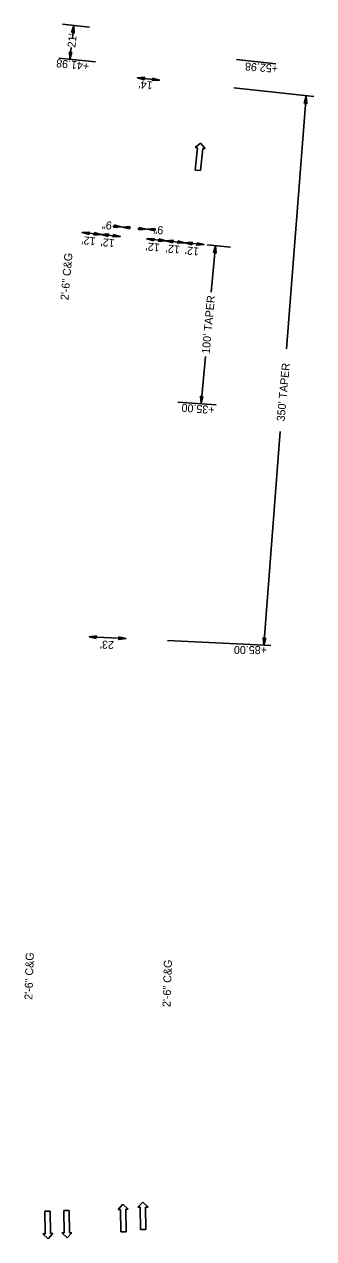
# Model space of a CAD drawing. Extents: x 2320991 to 2332664, y 598057 to 612602.
# Drawn here: x 2328339 to 2328520, y 605365 to 606124 of the extents above; entities that cross this region are included whole.
import ezdxf

# ---------------------------------------------------------------- set-up
doc = ezdxf.new("R2010")
doc.units = 0
for name, color, linetype in [('Prop Dimension', 7, 'Continuous'), ('Prop Dimension Text', 7, 'Continuous'), ('Prop Lane Arrow CELL', 7, 'Continuous'), ('Prop Terminator CELL', 7, 'Continuous')]:
    doc.layers.add(name, color=color, linetype=linetype)

msp = doc.modelspace()

# ---------------------------------------------------------------- linework, layer by layer
at = {"layer": 'Prop Dimension'}
for p, q in [((2328363.23, 606123.79), (2328380.1, 606121.92)), ((2328369.38, 606115.38), (2328370.23, 606123.02)), ((2328360.89, 606102.72), (2328383.94, 606100.24)), ((2328367.89, 606101.97), (2328368.71, 606109.29)), ((2328496.58, 606099.06), (2328472, 606101.75)), ((2328423.91, 606088.93), (2328409.99, 606090.41)), ((2328520.14, 606078.71), (2328470.33, 606084)), ((2328503.23, 605920.96), (2328515.34, 606078.8)), ((2328394.74, 605997.73), (2328399.95, 605997.21)), ((2328400.69, 605997.14), (2328405.9, 605996.62)), ((2328410.32, 605996.22), (2328415.54, 605995.83)), ((2328416.29, 605995.78), (2328421.51, 605995.39)), ((2328387.39, 605992.47), (2328375.45, 605993.67)), ((2328399.33, 605991.27), (2328387.39, 605992.47)), ((2328427.79, 605988.54), (2328415.85, 605989.74)), ((2328439.74, 605987.34), (2328427.8, 605988.54)), ((2328451.68, 605986.14), (2328439.74, 605987.34)), ((2328453.67, 605985.96), (2328468.17, 605984.63)), ((2328458.78, 605985.49), (2328456.13, 605956.47)), ((2328452.47, 605916.21), (2328449.79, 605886.89)), ((2328435.33, 605887.81), (2328459.18, 605886.04)), ((2328489.03, 605735.98), (2328499.27, 605869.41)), ((2328379.9, 605741.17), (2328402.88, 605740.07)), ((2328493.36, 605735.78), (2328428.85, 605738.84))]:
    msp.add_line(p, q, dxfattribs=at)
at = {"layer": 'Prop Lane Arrow CELL'}
for p, q in [((2328446.04, 606046.78), (2328449.44, 606049.6)), ((2328449.44, 606049.6), (2328452.3, 606046.14)), ((2328447.53, 606046.63), (2328446.04, 606046.78)), ((2328446.12, 606032.7), (2328447.53, 606046.63)), ((2328450.81, 606046.3), (2328449.4, 606032.37)), ((2328452.3, 606046.14), (2328450.81, 606046.3)), ((2328449.4, 606032.37), (2328446.12, 606032.7)), ((2328352.29, 605382.32), (2328355.59, 605382.36)), ((2328352.49, 605368.32), (2328352.29, 605382.32)), ((2328355.59, 605382.36), (2328355.79, 605368.36)), ((2328364.14, 605382.85), (2328367.44, 605382.9)), ((2328364.34, 605368.86), (2328364.14, 605382.85)), ((2328367.44, 605382.9), (2328367.63, 605368.9)), ((2328397.91, 605383.49), (2328400.96, 605386.68)), ((2328399.41, 605383.51), (2328397.91, 605383.49)), ((2328399.6, 605369.51), (2328399.41, 605383.51)), ((2328400.96, 605386.68), (2328404.21, 605383.58)), ((2328404.21, 605383.58), (2328402.71, 605383.55)), ((2328402.71, 605383.55), (2328402.9, 605369.56)), ((2328410.34, 605384.9), (2328413.4, 605388.09)), ((2328411.84, 605384.92), (2328410.34, 605384.9)), ((2328412.04, 605370.92), (2328411.84, 605384.92)), ((2328413.4, 605388.09), (2328416.64, 605384.98)), ((2328416.64, 605384.98), (2328415.14, 605384.96)), ((2328415.14, 605384.96), (2328415.34, 605370.96)), ((2328350.99, 605368.3), (2328352.49, 605368.32)), ((2328354.23, 605365.19), (2328350.99, 605368.3)), ((2328357.29, 605368.38), (2328354.23, 605365.19)), ((2328355.79, 605368.36), (2328357.29, 605368.38)), ((2328362.84, 605368.83), (2328364.34, 605368.86)), ((2328366.08, 605365.73), (2328362.84, 605368.83)), ((2328369.13, 605368.92), (2328366.08, 605365.73)), ((2328367.63, 605368.9), (2328369.13, 605368.92)), ((2328402.9, 605369.56), (2328399.6, 605369.51)), ((2328415.34, 605370.96), (2328412.04, 605370.92))]:
    msp.add_line(p, q, dxfattribs=at)
at = {"layer": 'Prop Terminator CELL'}
for points in [[(2328368.96, 606118.63), (2328370.23, 606123.02), (2328370.53, 606118.43), (2328369.79, 606119.09)], [(2328369.16, 606106.35), (2328367.89, 606101.97), (2328367.6, 606106.55), (2328368.33, 606105.89)], [(2328414.38, 606089.17), (2328409.99, 606090.41), (2328414.57, 606090.73), (2328413.92, 606090)], [(2328419.52, 606090.18), (2328423.91, 606088.93), (2328419.33, 606088.62), (2328419.98, 606089.35)], [(2328514.22, 606074.37), (2328515.34, 606078.8), (2328515.79, 606074.23), (2328515.04, 606074.86)], [(2328395.55, 605998.43), (2328399.95, 605997.21), (2328395.36, 605996.86), (2328396.02, 605997.6)], [(2328405.09, 605995.92), (2328400.69, 605997.14), (2328405.27, 605997.48), (2328404.62, 605996.74)], [(2328411.11, 605996.94), (2328415.54, 605995.83), (2328410.97, 605995.37), (2328411.6, 605996.13)], [(2328420.72, 605994.68), (2328416.29, 605995.78), (2328420.86, 605996.24), (2328420.23, 605995.49)], [(2328379.85, 605992.45), (2328375.45, 605993.67), (2328380.04, 605994.01), (2328379.38, 605993.28)], [(2328382.99, 605993.69), (2328387.39, 605992.47), (2328382.81, 605992.13), (2328383.46, 605992.87)], [(2328391.79, 605991.25), (2328387.39, 605992.47), (2328391.98, 605992.82), (2328391.32, 605992.08)], [(2328394.93, 605992.49), (2328399.33, 605991.27), (2328394.75, 605990.93), (2328395.4, 605991.67)], [(2328420.25, 605988.51), (2328415.85, 605989.74), (2328420.43, 605990.08), (2328419.78, 605989.34)], [(2328423.39, 605989.76), (2328427.79, 605988.54), (2328423.21, 605988.19), (2328423.86, 605988.93)], [(2328432.2, 605987.31), (2328427.8, 605988.54), (2328432.38, 605988.88), (2328431.73, 605988.14)], [(2328435.34, 605988.56), (2328439.74, 605987.34), (2328435.15, 605986.99), (2328435.81, 605987.73)], [(2328444.14, 605986.12), (2328439.74, 605987.34), (2328444.32, 605987.68), (2328443.67, 605986.94)], [(2328447.28, 605987.36), (2328451.68, 605986.14), (2328447.09, 605985.79), (2328447.75, 605986.53)], [(2328457.6, 605981.08), (2328458.78, 605985.49), (2328459.16, 605980.91), (2328458.42, 605981.56)], [(2328450.97, 605891.3), (2328449.79, 605886.89), (2328449.41, 605891.47), (2328450.15, 605890.83)], [(2328384.36, 605740.18), (2328379.9, 605741.17), (2328384.46, 605741.75), (2328383.85, 605740.98)], [(2328398.42, 605741.06), (2328402.88, 605740.07), (2328398.32, 605739.49), (2328398.93, 605740.26)], [(2328490.15, 605740.41), (2328489.03, 605735.98), (2328488.58, 605740.56), (2328489.33, 605739.92)]]:
    msp.add_lwpolyline(points, close=True, dxfattribs=at)

# ---------------------------------------------------------------- texts
at = {"layer": 'Prop Dimension'}
for s, rotation, p in [('+41.98', 174.08208, (2328380.11, 606099.89)), ('+52.98', 175.75062, (2328498, 606098.43)), ('+35.00', 175.75062, (2328458.38, 605885.26)), ('+85.00', 179.53628, (2328490.93, 605735.29))]:
    msp.add_text(s, height=5, rotation=rotation, dxfattribs=at).set_placement(p)
at = {"layer": 'Prop Dimension Text'}
for s, rotation, p in [("21'", 83.67, (2328371.24, 606109.01)), ("14'", 174.65138, (2328419.7, 606087.96)), ('9"', 174.2972, (2328394.31, 606000.44)), ('9"', 175.7822, (2328426.38, 605997.51)), ("12'", 174.26434, (2328384.09, 605990.57)), ("12'", 174.26434, (2328396.03, 605989.37)), ('2\'-6" C&G', 84.98733, (2328366.91, 605951.24)), ("12'", 174.26434, (2328424.2, 605986.67)), ("12'", 174.26434, (2328436.75, 605985.41)), ("12'", 174.26434, (2328448.69, 605984.21)), ("100' TAPER", 84.64157, (2328455.12, 605917.78)), ("350' TAPER", 84.64157, (2328501.92, 605875.57)), ("23'", 177.5227, (2328395.47, 605738.49)), ('2\'-6" C&G', 88.20185, (2328344.4, 605514.33)), ('2\'-6" C&G', 88.20185, (2328430.67, 605509.79))]:
    msp.add_text(s, height=5, rotation=rotation, dxfattribs=at).set_placement(p)

doc.saveas('drawing.dxf')
